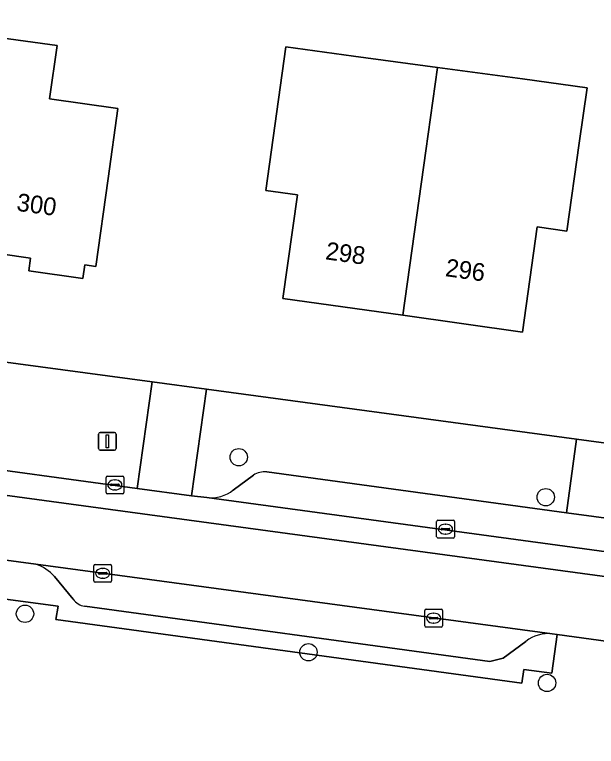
# Model space of a CAD drawing. Extents: x 161692 to 162379, y 380760 to 381678.
# Drawn here: x 161909.81 to 161942.62, y 380807.88 to 380849.13 of the extents above; entities that cross this region are included whole.
import ezdxf

# ---------------------------------------------------------------- set-up
doc = ezdxf.new("R2010")
doc.units = 0
for name, color, linetype in [('IMGEO_Berm_groen', 7, 'Continuous'), ('IMGEO_Boom', 7, 'Continuous'), ('IMGEO_Erf', 7, 'Continuous'), ('IMGEO_Kolk', 7, 'Continuous'), ('IMGEO_Lichtmast', 7, 'Continuous'), ('IMGEO_Pand', 7, 'Continuous'), ('IMGEO_Pand_nummerreeks', 7, 'Continuous'), ('IMGEO_Parkeervlak_open', 7, 'Continuous'), ('IMGEO_Rijbaan_lokaal_gesloten', 7, 'Continuous'), ('IMGEO_Voetpad_open', 7, 'Continuous')]:
    doc.layers.add(name, color=color, linetype=linetype)

msp = doc.modelspace()

# ---------------------------------------------------------------- linework, layer by layer
at = {"layer": 'IMGEO_Berm_groen'}
msp.add_lwpolyline([(161970.596, 380807.038), (161970.679, 380807.83), (161969.203, 380808.068), (161969.449, 380810.213), (161940.415, 380814.186), (161940.112, 380812.007), (161938.529, 380812.215), (161938.414, 380811.451), (161912.142, 380815.03), (161912.259, 380815.78), (161898.545, 380817.613)], dxfattribs=at)
at = {"layer": 'IMGEO_Boom'}
for centre in [(161922.452, 380824.183), (161939.764, 380821.929), (161910.395, 380815.354), (161926.382, 380813.188), (161939.838, 380811.455)]:
    msp.add_circle(centre, 0.489, dxfattribs=at)
at = {"layer": 'IMGEO_Erf'}
msp.add_lwpolyline([(161902.994, 380830.393), (161906.216, 380829.958), (161917.567, 380828.426), (161920.64, 380828.012), (161941.489, 380825.198), (161944.559, 380824.783), (161956.36, 380823.191), (161959.367, 380822.785), (161969.747, 380821.384), (161972.782, 380820.974), (161982.64, 380819.644), (161985.956, 380819.196), (162000, 380817.301), (162003.3, 380816.856), (162006.759, 380816.389), (162007.953, 380816.216), (162010.645, 380815.865), (162022.543, 380814.259), (162025.665, 380837.887), (162027.29, 380850.188), (162027.58, 380852.385)], dxfattribs=at)
for points in [[(161914.388, 380834.934), (161913.768, 380835.021), (161913.661, 380834.259), (161910.612, 380834.687), (161910.713, 380835.404), (161907.438, 380835.864), (161908.128, 380840.779), (161907.384, 380840.883), (161907.807, 380843.895), (161908.487, 380843.799), (161909.053, 380847.832), (161912.206, 380847.389), (161911.784, 380844.384), (161915.639, 380843.843), (161915.083, 380839.886)], [(161941.656, 380841.88), (161940.961, 380836.928), (161939.286, 380837.164), (161938.453, 380831.231), (161931.695, 380832.18), (161924.934, 380833.13), (161925.754, 380838.975), (161923.968, 380839.226), (161925.104, 380847.323), (161928.916, 380846.788), (161933.659, 380846.152), (161938.447, 380845.51), (161942.094, 380844.998)]]:
    msp.add_lwpolyline(points, close=True, dxfattribs=at)
at = {"layer": 'IMGEO_Kolk'}
for p, q in [((161914.963, 380822.195), (161914.963, 380823.047)), ((161915.038, 380823.121), (161915.89, 380823.121)), ((161915.451, 380822.901), (161915.476, 380822.901)), ((161915.964, 380823.047), (161915.964, 380822.195)), ((161915.222, 380822.615), (161915.222, 380822.627)), ((161915.66, 380822.578), (161915.262, 380822.578)), ((161915.265, 380822.664), (161915.663, 380822.664)), ((161915.474, 380822.341), (161915.449, 380822.341)), ((161915.706, 380822.627), (161915.706, 380822.615)), ((161915.89, 380822.121), (161915.038, 380822.121)), ((161933.611, 380819.701), (161933.611, 380820.553)), ((161933.686, 380820.627), (161934.538, 380820.627)), ((161934.099, 380820.407), (161934.124, 380820.407)), ((161934.612, 380820.553), (161934.612, 380819.701)), ((161933.87, 380820.121), (161933.87, 380820.133)), ((161934.308, 380820.084), (161933.91, 380820.084)), ((161933.913, 380820.17), (161934.311, 380820.17)), ((161934.122, 380819.847), (161934.097, 380819.847)), ((161934.354, 380820.133), (161934.354, 380820.121)), ((161934.538, 380819.627), (161933.686, 380819.627)), ((161914.28, 380817.21), (161914.28, 380818.062)), ((161914.355, 380818.136), (161915.207, 380818.136)), ((161914.768, 380817.916), (161914.793, 380817.916)), ((161915.281, 380818.062), (161915.281, 380817.21)), ((161914.539, 380817.63), (161914.539, 380817.642)), ((161914.977, 380817.593), (161914.579, 380817.593)), ((161914.582, 380817.679), (161914.98, 380817.679)), ((161915.023, 380817.642), (161915.023, 380817.63)), ((161915.207, 380817.136), (161914.355, 380817.136)), ((161914.791, 380817.356), (161914.766, 380817.356)), ((161932.937, 380814.684), (161932.937, 380815.536)), ((161933.012, 380815.61), (161933.864, 380815.61)), ((161933.425, 380815.39), (161933.45, 380815.39)), ((161933.938, 380815.536), (161933.938, 380814.684)), ((161933.196, 380815.104), (161933.196, 380815.116)), ((161933.634, 380815.067), (161933.236, 380815.067)), ((161933.239, 380815.153), (161933.637, 380815.153)), ((161933.68, 380815.116), (161933.68, 380815.104)), ((161933.864, 380814.61), (161933.012, 380814.61)), ((161933.448, 380814.83), (161933.423, 380814.83))]:
    msp.add_line(p, q, dxfattribs=at)
for points in [[(161914.963, 380822.195), (161914.963, 380823.047)], [(161915.038, 380823.121), (161915.89, 380823.121)], [(161915.964, 380823.047), (161915.964, 380822.195)], [(161915.89, 380822.121), (161915.038, 380822.121)], [(161933.611, 380819.701), (161933.611, 380820.553)], [(161933.686, 380820.627), (161934.538, 380820.627)], [(161934.612, 380820.553), (161934.612, 380819.701)], [(161934.538, 380819.627), (161933.686, 380819.627)], [(161914.28, 380817.21), (161914.28, 380818.062)], [(161914.355, 380818.136), (161915.207, 380818.136)], [(161915.281, 380818.062), (161915.281, 380817.21)], [(161915.207, 380817.136), (161914.355, 380817.136)], [(161932.937, 380814.684), (161932.937, 380815.536)], [(161933.012, 380815.61), (161933.864, 380815.61)], [(161933.938, 380815.536), (161933.938, 380814.684)], [(161933.864, 380814.61), (161933.012, 380814.61)]]:
    msp.add_lwpolyline(points, dxfattribs=at)
for centre, radius, start, end in [((161915.04, 380823.045), 0.0765, 91.552, 178.448), ((161915.04, 380823.045), 0.0765, 91.552, 178.448), ((161915.888, 380823.045), 0.0765, 1.552, 88.448), ((161915.888, 380823.045), 0.0765, 1.552, 88.448), ((161915.262, 380822.624), 0.0403, 85.8775, 175.7526), ((161915.259, 380822.614), 0.0366, 178.938, 274.7102), ((161915.663, 380822.621), 0.043, 264.8664, 352.4533), ((161915.667, 380822.626), 0.0386, 1.7309, 96.639), ((161915.04, 380822.197), 0.0765, 181.552, 268.448), ((161915.04, 380822.197), 0.0765, 181.552, 268.448), ((161915.888, 380822.197), 0.0765, 271.552, 358.448), ((161915.888, 380822.197), 0.0765, 271.552, 358.448), ((161933.688, 380820.551), 0.0765, 91.552, 178.448), ((161933.688, 380820.551), 0.0765, 91.552, 178.448), ((161934.536, 380820.551), 0.0765, 1.552, 88.448), ((161934.536, 380820.551), 0.0765, 1.552, 88.448), ((161933.91, 380820.13), 0.0403, 85.8775, 175.7526), ((161933.907, 380820.12), 0.0366, 178.938, 274.7102), ((161934.311, 380820.127), 0.043, 264.8664, 352.4533), ((161934.315, 380820.132), 0.0386, 1.7309, 96.639), ((161933.688, 380819.703), 0.0765, 181.552, 268.448), ((161933.688, 380819.703), 0.0765, 181.552, 268.448), ((161934.536, 380819.703), 0.0765, 271.552, 358.448), ((161934.536, 380819.703), 0.0765, 271.552, 358.448), ((161914.357, 380818.06), 0.0765, 91.552, 178.448), ((161914.357, 380818.06), 0.0765, 91.552, 178.448), ((161915.205, 380818.06), 0.0765, 1.552, 88.448), ((161915.205, 380818.06), 0.0765, 1.552, 88.448), ((161914.579, 380817.639), 0.0403, 85.8775, 175.7526), ((161914.576, 380817.629), 0.0366, 178.938, 274.7102), ((161914.98, 380817.636), 0.043, 264.8664, 352.4533), ((161914.984, 380817.641), 0.0386, 1.7309, 96.639), ((161914.357, 380817.212), 0.0765, 181.552, 268.448), ((161914.357, 380817.212), 0.0765, 181.552, 268.448), ((161915.205, 380817.212), 0.0765, 271.552, 358.448), ((161915.205, 380817.212), 0.0765, 271.552, 358.448), ((161933.014, 380815.534), 0.0765, 91.552, 178.448), ((161933.014, 380815.534), 0.0765, 91.552, 178.448), ((161933.862, 380815.534), 0.0765, 1.552, 88.448), ((161933.862, 380815.534), 0.0765, 1.552, 88.448), ((161933.236, 380815.113), 0.0403, 85.8775, 175.7526), ((161933.233, 380815.103), 0.0366, 178.938, 274.7102), ((161933.637, 380815.11), 0.043, 264.8664, 352.4533), ((161933.641, 380815.115), 0.0386, 1.7309, 96.639), ((161933.014, 380814.686), 0.0765, 181.552, 268.448), ((161933.014, 380814.686), 0.0765, 181.552, 268.448), ((161933.862, 380814.686), 0.0765, 271.552, 358.448), ((161933.862, 380814.686), 0.0765, 271.552, 358.448)]:
    msp.add_arc(centre, radius, start, end, dxfattribs=at)
for centre, major_axis, ratio, start_param, end_param in [((161915.45, 380822.621), (-0.387, 0.002), 0.722429, 4.712389, 7.853982), ((161915.475, 380822.621), (-0.39, 0.002), 0.717154, 1.570796, 4.712389), ((161934.098, 380820.127), (-0.387, 0.002), 0.722429, 4.712389, 7.853982), ((161934.123, 380820.127), (-0.39, 0.002), 0.717154, 1.570796, 4.712389), ((161914.767, 380817.636), (-0.387, 0.002), 0.722429, 4.712389, 7.853982), ((161914.792, 380817.636), (-0.39, 0.002), 0.717154, 1.570796, 4.712389), ((161933.424, 380815.11), (-0.387, 0.002), 0.722429, 4.712389, 7.853982), ((161933.449, 380815.11), (-0.39, 0.002), 0.717154, 1.570796, 4.712389)]:
    msp.add_ellipse(centre, major_axis=major_axis, ratio=ratio, start_param=start_param, end_param=end_param, dxfattribs=at)
at = {"layer": 'IMGEO_Lichtmast'}
for p, q in [((161914.543, 380824.676), (161914.543, 380825.476)), ((161914.543, 380825.476), (161914.543, 380824.676)), ((161914.643, 380825.576), (161915.433, 380825.576)), ((161915.433, 380825.576), (161914.643, 380825.576)), ((161915.533, 380825.476), (161915.533, 380824.676)), ((161915.533, 380824.676), (161915.533, 380825.476)), ((161915.433, 380824.576), (161914.643, 380824.576)), ((161914.643, 380824.576), (161915.433, 380824.576))]:
    msp.add_line(p, q, dxfattribs=at)
msp.add_lwpolyline([(161914.963, 380825.451), (161915.113, 380825.451), (161915.113, 380824.701), (161914.963, 380824.701), (161914.963, 380825.451)], dxfattribs=at)
for centre, start, end in [((161914.643, 380825.476), 90, 180), ((161914.643, 380825.476), 90, 180), ((161915.433, 380825.476), 0, 90), ((161915.433, 380825.476), 360, 90), ((161914.643, 380824.676), 180, 270), ((161914.643, 380824.676), 180, 270), ((161915.433, 380824.676), 270, 0), ((161915.433, 380824.676), 270, 0)]:
    msp.add_arc(centre, 0.1, start, end, dxfattribs=at)
at = {"layer": 'IMGEO_Pand'}
for points in [[(161915.083, 380839.886), (161915.639, 380843.843), (161911.784, 380844.384), (161912.206, 380847.389), (161909.053, 380847.832), (161908.487, 380843.799), (161907.807, 380843.895), (161907.384, 380840.883), (161908.128, 380840.779), (161907.438, 380835.864), (161910.713, 380835.404), (161910.612, 380834.687), (161913.661, 380834.259), (161913.768, 380835.021), (161914.388, 380834.934)], [(161933.659, 380846.152), (161928.916, 380846.788), (161925.104, 380847.323), (161923.968, 380839.226), (161925.754, 380838.975), (161924.934, 380833.13), (161931.695, 380832.18), (161932.998, 380841.452)], [(161933.659, 380846.152), (161932.998, 380841.452), (161931.695, 380832.18), (161938.453, 380831.231), (161939.286, 380837.164), (161940.961, 380836.928), (161941.656, 380841.88), (161942.094, 380844.998), (161938.447, 380845.51)]]:
    msp.add_lwpolyline(points, close=True, dxfattribs=at)
at = {"layer": 'IMGEO_Parkeervlak_open'}
for points in [[(161923.275, 380823.168), (161922.142, 380822.333)], [(162016.852, 380810.742), (162010.075, 380811.66), (162007.385, 380812.025), (162006.192, 380812.187), (162002.733, 380812.656), (161985.346, 380815.014), (161982.089, 380815.455), (161972.239, 380816.792), (161969.295, 380817.193), (161958.799, 380818.621), (161955.808, 380819.028), (161944.021, 380820.632), (161940.941, 380821.051), (161924.029, 380823.352)], [(161920.649, 380821.91), (162019.525, 380808.483)], [(161940.127, 380814.227), (161910.997, 380818.145)], [(161912.052, 380817.45), (161913.112, 380816.175)], [(161913.76, 380815.782), (161936.613, 380812.668), (161937.361, 380812.86), (161938.64, 380813.802)]]:
    msp.add_lwpolyline(points, dxfattribs=at)
for centre, radius, start, end in [((161923.899, 380822.247), 1.113, 83.305, 124.1229), ((161920.896, 380823.883), 1.988, 262.8519, 308.7853), ((161910.363, 380816.035), 2.203, 39.9624, 73.2864), ((161913.91, 380816.761), 0.99, 216.2639, 261.264), ((161939.913, 380812.162), 2.076, 84.0832, 127.8178)]:
    msp.add_arc(centre, radius, start, end, dxfattribs=at)
at = {"layer": 'IMGEO_Rijbaan_lokaal_gesloten'}
for points in [[(161814.137, 380834.931), (162153.114, 380788.982), (162173.589, 380787.538), (162178.941, 380786.895), (162192.055, 380785.129), (162226.418, 380780.403), (162229.289, 380780.178), (162234.771, 380780.432)], [(162234.785, 380779.843), (162234.771, 380780.432), (162229.289, 380780.178), (162226.418, 380780.403), (162192.055, 380785.129), (162178.941, 380786.895), (162173.589, 380787.538), (162153.114, 380788.982), (161814.137, 380834.931)], [(161785.735, 380831.837), (161803.94, 380831.083), (161806.77, 380830.885), (161820.431, 380830.418), (161834.49, 380828.566), (161845.222, 380827.099), (161887.661, 380821.279), (161891.404, 380820.778), (161898.822, 380819.796), (161910.997, 380818.145), (161940.127, 380814.227), (161940.415, 380814.186), (161969.449, 380810.213), (161970.442, 380810.065), (161999.463, 380806.128), (162000.665, 380805.971), (162035.924, 380801.201), (162040.702, 380800.555), (162059.025, 380798.069)], [(161916.716, 380822.41), (161905.409, 380823.96)], [(161919.794, 380822.011), (161916.716, 380822.41)], [(161920.649, 380821.91), (161919.794, 380822.011)], [(162019.525, 380808.483), (161920.649, 380821.91)]]:
    msp.add_lwpolyline(points, dxfattribs=at)
at = {"layer": 'IMGEO_Voetpad_open'}
for points in [[(161906.216, 380829.958), (161905.409, 380823.96), (161916.716, 380822.41), (161917.567, 380828.426)], [(161917.567, 380828.426), (161916.716, 380822.41), (161919.794, 380822.011), (161920.64, 380828.012)], [(161941.489, 380825.198), (161940.941, 380821.051), (161944.021, 380820.632), (161944.559, 380824.783)]]:
    msp.add_lwpolyline(points, close=True, dxfattribs=at)
for points in [[(161924.029, 380823.352), (161940.941, 380821.051), (161941.489, 380825.198), (161920.64, 380828.012), (161919.794, 380822.011), (161920.649, 380821.91)], [(161922.142, 380822.333), (161923.275, 380823.168)], [(161910.997, 380818.145), (161898.822, 380819.796)], [(161896.434, 380802.094), (161897.597, 380801.932), (161897.799, 380803.337), (161896.59, 380803.512), (161898.545, 380817.613), (161912.259, 380815.78), (161912.142, 380815.03), (161938.414, 380811.451), (161938.529, 380812.215), (161940.112, 380812.007), (161940.415, 380814.186), (161940.127, 380814.227)], [(161913.112, 380816.175), (161912.052, 380817.45)], [(161938.64, 380813.802), (161937.361, 380812.86), (161936.613, 380812.668), (161913.76, 380815.782)]]:
    msp.add_lwpolyline(points, dxfattribs=at)
for centre, radius, start, end in [((161923.899, 380822.247), 1.113, 83.305, 124.1229), ((161920.896, 380823.883), 1.988, 262.8519, 308.7853), ((161910.363, 380816.035), 2.203, 39.9624, 73.2864), ((161913.91, 380816.761), 0.99, 216.2639, 261.264), ((161939.913, 380812.162), 2.076, 84.0832, 127.8178)]:
    msp.add_arc(centre, radius, start, end, dxfattribs=at)

# ---------------------------------------------------------------- texts
at = {"layer": 'IMGEO_Pand_nummerreeks'}
for s, rotation, p in [('300', 352.3784, (161909.884, 380838.079)), ('298', 352.004, (161927.302, 380835.342)), ('296', 352.004, (161934.059, 380834.394))]:
    msp.add_text(s, height=1, rotation=rotation, dxfattribs=at).set_placement(p)

doc.saveas('drawing.dxf')
